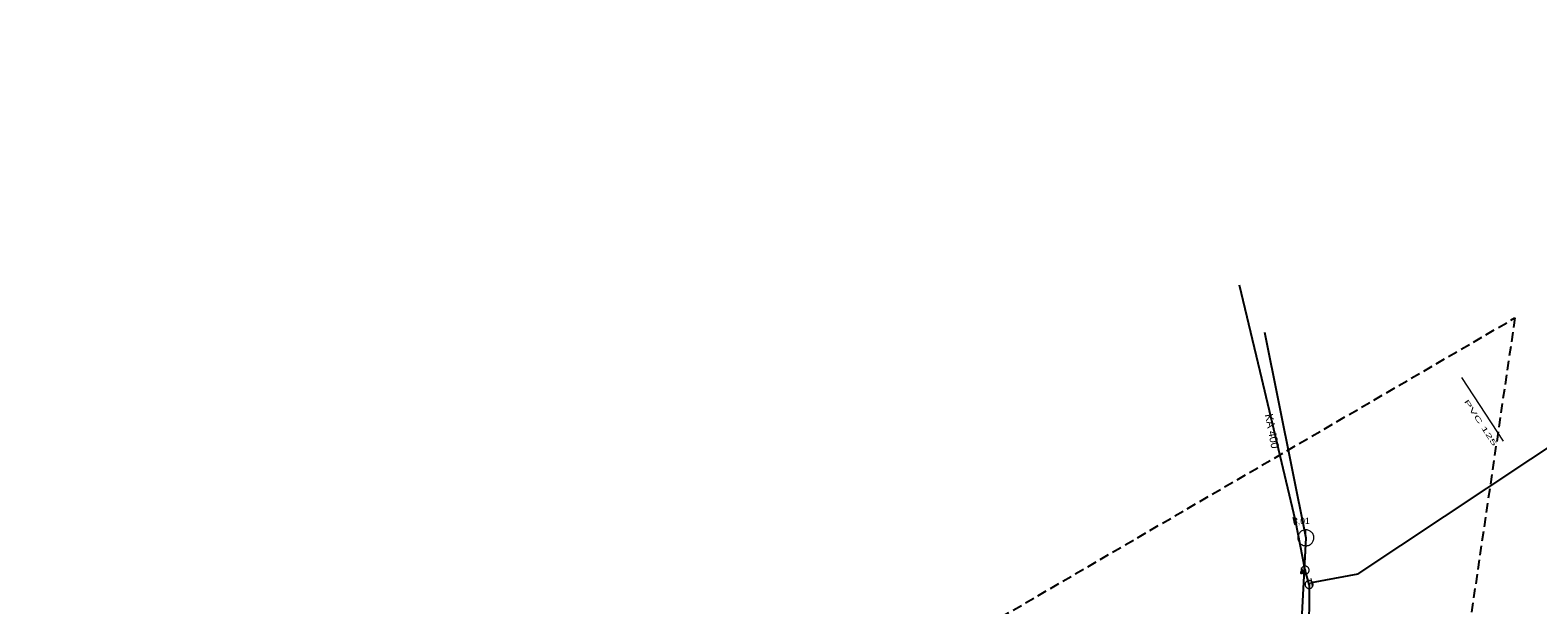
# Model space of a CAD drawing. Extents: x -689189 to -688666, y -973229 to -972850.
# Drawn here: x -688952.7 to -688764.3, y -972922 to -972850.1 of the extents above; entities that cross this region are included whole.
import ezdxf

# ---------------------------------------------------------------- set-up
doc = ezdxf.new("R2010")
doc.units = 0
doc.header["$LTSCALE"] = 0.4
doc.linetypes.add('MEDIUM_DASHED', pattern=[4.5, 3, -1.5])
doc.layers.add('1', color=7, linetype='Continuous')
for name, color, linetype, lineweight in [('11', 7, 'Continuous', 13), ('14', 7, 'Continuous', 13), ('17', 7, 'Continuous', 25), ('22', 7, 'Continuous', 13), ('34', 7, 'Continuous', 13), ('47', 7, 'Continuous', 13), ('63', 7, 'MEDIUM_DASHED', 25), ('9', 7, 'Continuous', 13)]:
    doc.layers.add(name, color=color, linetype=linetype, lineweight=lineweight)

msp = doc.modelspace()

# ---------------------------------------------------------------- linework, layer by layer
at = {"layer": '11'}
msp.add_line((-688773.829, -972893.57), (-688768.609, -972901.5), dxfattribs=at)
at = {"layer": '14', "lineweight": 25}
for p, q in [((-688798.458, -972887.895), (-688793.27, -972913.607)), ((-688793.27, -972913.607), (-688794.848, -972944.059))]:
    msp.add_line(p, q, dxfattribs=at)
at = {"layer": '14'}
for p, q in [((-688794.559, -972911.458), (-688794.779, -972911.519)), ((-688793.649, -972917.78), (-688793.829, -972917.959)), ((-688793.357, -972917.65), (-688793.65, -972917.78)), ((-688792.569, -972919.209), (-688792.866, -972919.454))]:
    msp.add_line(p, q, dxfattribs=at)
at = {"layer": '17'}
for q in [(-688793.357, -972917.649), (-688792.912, -972931.053)]:
    msp.add_line((-688792.866, -972919.454), q, dxfattribs=at)
for points in [[(-688792.569, -972919.209), (-688786.753, -972918.126), (-688749.036, -972893.049), (-688728.665, -972879.484), (-688714.517, -972870.393), (-688697.101, -972861.767), (-688696.793, -972861.66), (-688668.989, -972850.105), (-688665.589, -972858.071)], [(-688793.357, -972917.649), (-688794.559, -972911.458), (-688798.977, -972892.802), (-688801.561, -972882.007)]]:
    msp.add_lwpolyline(points, dxfattribs=at)
at = {"layer": '22'}
msp.add_line((-688793.27, -972915.607), (-688793.269, -972912.607), dxfattribs=at)
msp.add_lwpolyline([(-688792.27, -972913.607), (-688792.275, -972913.498), (-688792.293, -972913.39), (-688792.323, -972913.284), (-688792.363, -972913.183), (-688792.415, -972913.086), (-688792.477, -972912.996), (-688792.549, -972912.913), (-688792.629, -972912.839), (-688792.717, -972912.773), (-688792.811, -972912.718), (-688792.911, -972912.673), (-688793.016, -972912.64), (-688793.123, -972912.618), (-688793.232, -972912.608), (-688793.342, -972912.61), (-688793.45, -972912.624), (-688793.557, -972912.649), (-688793.66, -972912.686), (-688793.758, -972912.735), (-688793.85, -972912.793), (-688793.936, -972912.862), (-688794.013, -972912.939), (-688794.082, -972913.025), (-688794.141, -972913.117), (-688794.189, -972913.215), (-688794.226, -972913.318), (-688794.252, -972913.425), (-688794.266, -972913.533), (-688794.269, -972913.643), (-688794.259, -972913.752), (-688794.238, -972913.859), (-688794.204, -972913.963), (-688794.16, -972914.063), (-688794.105, -972914.158), (-688794.039, -972914.246), (-688793.965, -972914.326), (-688793.882, -972914.398), (-688793.792, -972914.46), (-688793.696, -972914.512), (-688793.594, -972914.553), (-688793.489, -972914.583), (-688793.381, -972914.601), (-688793.271, -972914.607), (-688793.162, -972914.601), (-688793.054, -972914.583), (-688792.949, -972914.554), (-688792.847, -972914.513), (-688792.75, -972914.461), (-688792.66, -972914.399), (-688792.577, -972914.328), (-688792.502, -972914.248), (-688792.437, -972914.16), (-688792.381, -972914.066), (-688792.337, -972913.966), (-688792.303, -972913.862), (-688792.281, -972913.754), (-688792.271, -972913.645)], close=True, dxfattribs=at)
at = {"layer": '34'}
for p, q in [((-688794.914, -972911.037), (-688794.644, -972912)), ((-688793.852, -972917.323), (-688793.446, -972918.237)), ((-688792.637, -972918.713), (-688792.501, -972919.704))]:
    msp.add_line(p, q, dxfattribs=at)
at = {"layer": '47'}
for points in [[(-688793.452, -972917.158), (-688793.502, -972917.171), (-688793.552, -972917.188), (-688793.598, -972917.212), (-688793.643, -972917.239), (-688793.684, -972917.271), (-688793.722, -972917.308), (-688793.755, -972917.348), (-688793.784, -972917.391), (-688793.809, -972917.437), (-688793.829, -972917.486), (-688793.844, -972917.536), (-688793.852, -972917.588), (-688793.856, -972917.64), (-688793.854, -972917.692), (-688793.847, -972917.744), (-688793.834, -972917.794), (-688793.817, -972917.844), (-688793.793, -972917.891), (-688793.766, -972917.935), (-688793.734, -972917.976), (-688793.697, -972918.014), (-688793.657, -972918.048), (-688793.613, -972918.077), (-688793.568, -972918.102), (-688793.519, -972918.121), (-688793.469, -972918.136), (-688793.417, -972918.145), (-688793.365, -972918.148), (-688793.313, -972918.146), (-688793.261, -972918.139), (-688793.211, -972918.126), (-688793.161, -972918.109), (-688793.114, -972918.086), (-688793.07, -972918.058), (-688793.029, -972918.026), (-688792.991, -972917.99), (-688792.957, -972917.95), (-688792.927, -972917.906), (-688792.903, -972917.86), (-688792.884, -972917.811), (-688792.869, -972917.761), (-688792.86, -972917.71), (-688792.857, -972917.657), (-688792.859, -972917.605), (-688792.866, -972917.553), (-688792.879, -972917.503), (-688792.896, -972917.453), (-688792.919, -972917.407), (-688792.947, -972917.362), (-688792.979, -972917.321), (-688793.015, -972917.283), (-688793.055, -972917.25), (-688793.098, -972917.22), (-688793.145, -972917.196), (-688793.194, -972917.176), (-688793.244, -972917.161), (-688793.295, -972917.153), (-688793.348, -972917.149), (-688793.4, -972917.151)], [(-688793.372, -972917.568), (-688793.381, -972917.57), (-688793.388, -972917.573), (-688793.396, -972917.577), (-688793.403, -972917.581), (-688793.41, -972917.587), (-688793.416, -972917.593), (-688793.422, -972917.599), (-688793.427, -972917.606), (-688793.43, -972917.614), (-688793.434, -972917.622), (-688793.436, -972917.63), (-688793.438, -972917.639), (-688793.438, -972917.647), (-688793.439, -972917.655), (-688793.437, -972917.664), (-688793.435, -972917.673), (-688793.432, -972917.68), (-688793.428, -972917.688), (-688793.424, -972917.695), (-688793.418, -972917.702), (-688793.412, -972917.708), (-688793.406, -972917.714), (-688793.399, -972917.719), (-688793.391, -972917.723), (-688793.383, -972917.726), (-688793.375, -972917.728), (-688793.366, -972917.73), (-688793.358, -972917.73), (-688793.35, -972917.731), (-688793.341, -972917.729), (-688793.332, -972917.727), (-688793.325, -972917.724), (-688793.317, -972917.72), (-688793.31, -972917.716), (-688793.303, -972917.71), (-688793.297, -972917.705), (-688793.291, -972917.698), (-688793.286, -972917.691), (-688793.282, -972917.683), (-688793.279, -972917.675), (-688793.277, -972917.667), (-688793.275, -972917.658), (-688793.275, -972917.65), (-688793.274, -972917.642), (-688793.276, -972917.633), (-688793.278, -972917.624), (-688793.281, -972917.617), (-688793.285, -972917.609), (-688793.289, -972917.602), (-688793.295, -972917.595), (-688793.3, -972917.589), (-688793.307, -972917.583), (-688793.314, -972917.578), (-688793.322, -972917.575), (-688793.33, -972917.571), (-688793.338, -972917.569), (-688793.347, -972917.567), (-688793.355, -972917.567), (-688793.363, -972917.566)], [(-688792.67, -972919.914), (-688792.623, -972919.891), (-688792.579, -972919.863), (-688792.538, -972919.831), (-688792.5, -972919.795), (-688792.466, -972919.754), (-688792.437, -972919.711), (-688792.413, -972919.665), (-688792.393, -972919.616), (-688792.379, -972919.566), (-688792.369, -972919.514), (-688792.366, -972919.462), (-688792.368, -972919.41), (-688792.375, -972919.358), (-688792.388, -972919.307), (-688792.405, -972919.258), (-688792.428, -972919.211), (-688792.456, -972919.167), (-688792.489, -972919.125), (-688792.524, -972919.088), (-688792.565, -972919.054), (-688792.608, -972919.025), (-688792.655, -972919), (-688792.703, -972918.981), (-688792.753, -972918.966), (-688792.805, -972918.957), (-688792.857, -972918.954), (-688792.91, -972918.955), (-688792.961, -972918.963), (-688793.012, -972918.976), (-688793.061, -972918.993), (-688793.108, -972919.016), (-688793.152, -972919.044), (-688793.194, -972919.076), (-688793.231, -972919.112), (-688793.265, -972919.153), (-688793.294, -972919.196), (-688793.319, -972919.242), (-688793.339, -972919.29), (-688793.353, -972919.341), (-688793.362, -972919.393), (-688793.365, -972919.445), (-688793.364, -972919.497), (-688793.356, -972919.549), (-688793.343, -972919.6), (-688793.326, -972919.649), (-688793.303, -972919.696), (-688793.275, -972919.74), (-688793.244, -972919.781), (-688793.207, -972919.819), (-688793.166, -972919.853), (-688793.123, -972919.882), (-688793.077, -972919.906), (-688793.029, -972919.926), (-688792.978, -972919.94), (-688792.926, -972919.95), (-688792.874, -972919.953), (-688792.823, -972919.951), (-688792.77, -972919.944), (-688792.719, -972919.931)], [(-688792.833, -972919.529), (-688792.825, -972919.525), (-688792.819, -972919.521), (-688792.812, -972919.516), (-688792.806, -972919.51), (-688792.8, -972919.503), (-688792.796, -972919.496), (-688792.791, -972919.488), (-688792.788, -972919.48), (-688792.786, -972919.472), (-688792.784, -972919.464), (-688792.784, -972919.455), (-688792.784, -972919.446), (-688792.785, -972919.438), (-688792.787, -972919.43), (-688792.79, -972919.421), (-688792.794, -972919.413), (-688792.798, -972919.407), (-688792.803, -972919.4), (-688792.809, -972919.394), (-688792.816, -972919.388), (-688792.823, -972919.384), (-688792.831, -972919.379), (-688792.839, -972919.376), (-688792.847, -972919.373), (-688792.855, -972919.372), (-688792.864, -972919.372), (-688792.873, -972919.372), (-688792.881, -972919.373), (-688792.889, -972919.375), (-688792.898, -972919.378), (-688792.906, -972919.382), (-688792.912, -972919.386), (-688792.919, -972919.391), (-688792.925, -972919.397), (-688792.931, -972919.404), (-688792.936, -972919.411), (-688792.94, -972919.419), (-688792.943, -972919.427), (-688792.946, -972919.435), (-688792.947, -972919.443), (-688792.947, -972919.452), (-688792.947, -972919.461), (-688792.946, -972919.469), (-688792.944, -972919.477), (-688792.941, -972919.486), (-688792.937, -972919.494), (-688792.933, -972919.5), (-688792.928, -972919.507), (-688792.922, -972919.513), (-688792.915, -972919.519), (-688792.908, -972919.524), (-688792.9, -972919.528), (-688792.892, -972919.531), (-688792.884, -972919.533), (-688792.876, -972919.535), (-688792.867, -972919.535), (-688792.858, -972919.535), (-688792.85, -972919.534), (-688792.842, -972919.532)]]:
    msp.add_lwpolyline(points, close=True, dxfattribs=at)
at = {"layer": '63'}
msp.add_lwpolyline([(-689164.065, -973177.51), (-689187.511, -973131.176), (-688767.155, -972886.107), (-688767.155, -972886.107), (-688777.761, -972958.121), (-688777.761, -972958.121), (-688989.335, -973072.002), (-688989.335, -973072.002)], close=True, dxfattribs=at)
at = {"layer": '9'}
for points in [[(-688793.955, -972917.959), (-688793.955, -972917.972), (-688793.953, -972917.985), (-688793.95, -972917.998), (-688793.945, -972918.01), (-688793.939, -972918.022), (-688793.932, -972918.033), (-688793.924, -972918.043), (-688793.914, -972918.053), (-688793.904, -972918.061), (-688793.893, -972918.068), (-688793.881, -972918.074), (-688793.869, -972918.079), (-688793.856, -972918.082), (-688793.843, -972918.084), (-688793.83, -972918.086), (-688793.817, -972918.085), (-688793.804, -972918.083), (-688793.791, -972918.08), (-688793.779, -972918.075), (-688793.767, -972918.069), (-688793.756, -972918.062), (-688793.746, -972918.054), (-688793.736, -972918.044), (-688793.728, -972918.034), (-688793.721, -972918.023), (-688793.715, -972918.011), (-688793.71, -972917.999), (-688793.707, -972917.986), (-688793.705, -972917.973), (-688793.703, -972917.96), (-688793.704, -972917.947), (-688793.706, -972917.934), (-688793.709, -972917.921), (-688793.714, -972917.909), (-688793.72, -972917.897), (-688793.727, -972917.886), (-688793.735, -972917.876), (-688793.745, -972917.866), (-688793.755, -972917.858), (-688793.766, -972917.851), (-688793.778, -972917.845), (-688793.79, -972917.84), (-688793.803, -972917.837), (-688793.816, -972917.835), (-688793.829, -972917.834), (-688793.842, -972917.834), (-688793.855, -972917.836), (-688793.868, -972917.839), (-688793.88, -972917.844), (-688793.892, -972917.85), (-688793.903, -972917.857), (-688793.913, -972917.865), (-688793.923, -972917.875), (-688793.931, -972917.885), (-688793.938, -972917.896), (-688793.944, -972917.908), (-688793.949, -972917.92), (-688793.952, -972917.933), (-688793.954, -972917.946)], [(-688793.935, -972917.959), (-688793.936, -972917.97), (-688793.934, -972917.981), (-688793.931, -972917.992), (-688793.927, -972918.002), (-688793.922, -972918.012), (-688793.916, -972918.021), (-688793.909, -972918.03), (-688793.901, -972918.038), (-688793.892, -972918.045), (-688793.883, -972918.051), (-688793.873, -972918.056), (-688793.863, -972918.06), (-688793.852, -972918.063), (-688793.841, -972918.066), (-688793.83, -972918.066), (-688793.819, -972918.066), (-688793.808, -972918.064), (-688793.797, -972918.061), (-688793.787, -972918.057), (-688793.777, -972918.052), (-688793.768, -972918.046), (-688793.759, -972918.039), (-688793.751, -972918.031), (-688793.744, -972918.022), (-688793.738, -972918.013), (-688793.733, -972918.003), (-688793.729, -972917.993), (-688793.726, -972917.982), (-688793.724, -972917.971), (-688793.723, -972917.96), (-688793.723, -972917.949), (-688793.725, -972917.938), (-688793.728, -972917.927), (-688793.732, -972917.917), (-688793.737, -972917.907), (-688793.743, -972917.898), (-688793.75, -972917.889), (-688793.758, -972917.881), (-688793.767, -972917.874), (-688793.776, -972917.868), (-688793.786, -972917.863), (-688793.796, -972917.859), (-688793.807, -972917.856), (-688793.818, -972917.854), (-688793.829, -972917.854), (-688793.84, -972917.853), (-688793.851, -972917.855), (-688793.862, -972917.858), (-688793.872, -972917.862), (-688793.882, -972917.867), (-688793.891, -972917.873), (-688793.9, -972917.88), (-688793.908, -972917.888), (-688793.915, -972917.897), (-688793.921, -972917.906), (-688793.926, -972917.916), (-688793.93, -972917.926), (-688793.933, -972917.937), (-688793.935, -972917.948)], [(-688793.916, -972917.959), (-688793.916, -972917.968), (-688793.915, -972917.977), (-688793.912, -972917.986), (-688793.909, -972917.994), (-688793.905, -972918.002), (-688793.9, -972918.01), (-688793.894, -972918.017), (-688793.888, -972918.023), (-688793.881, -972918.029), (-688793.873, -972918.034), (-688793.865, -972918.038), (-688793.857, -972918.041), (-688793.848, -972918.044), (-688793.839, -972918.045), (-688793.83, -972918.047), (-688793.821, -972918.046), (-688793.812, -972918.045), (-688793.803, -972918.042), (-688793.795, -972918.039), (-688793.787, -972918.035), (-688793.779, -972918.03), (-688793.772, -972918.024), (-688793.766, -972918.018), (-688793.76, -972918.011), (-688793.755, -972918.003), (-688793.751, -972917.995), (-688793.748, -972917.987), (-688793.745, -972917.978), (-688793.744, -972917.969), (-688793.742, -972917.96), (-688793.743, -972917.951), (-688793.744, -972917.942), (-688793.747, -972917.933), (-688793.75, -972917.925), (-688793.754, -972917.917), (-688793.759, -972917.909), (-688793.765, -972917.902), (-688793.771, -972917.896), (-688793.778, -972917.89), (-688793.786, -972917.885), (-688793.794, -972917.881), (-688793.802, -972917.878), (-688793.811, -972917.875), (-688793.82, -972917.874), (-688793.829, -972917.873), (-688793.838, -972917.873), (-688793.847, -972917.874), (-688793.856, -972917.877), (-688793.864, -972917.88), (-688793.872, -972917.884), (-688793.88, -972917.889), (-688793.887, -972917.895), (-688793.893, -972917.901), (-688793.899, -972917.908), (-688793.904, -972917.916), (-688793.908, -972917.924), (-688793.911, -972917.932), (-688793.914, -972917.941), (-688793.915, -972917.95)], [(-688793.896, -972917.959), (-688793.896, -972917.966), (-688793.895, -972917.973), (-688793.894, -972917.98), (-688793.891, -972917.986), (-688793.888, -972917.992), (-688793.884, -972917.998), (-688793.88, -972918.004), (-688793.875, -972918.009), (-688793.869, -972918.013), (-688793.863, -972918.017), (-688793.857, -972918.02), (-688793.851, -972918.023), (-688793.844, -972918.024), (-688793.837, -972918.027), (-688793.83, -972918.027), (-688793.823, -972918.027), (-688793.816, -972918.025), (-688793.809, -972918.024), (-688793.803, -972918.021), (-688793.796, -972918.018), (-688793.791, -972918.014), (-688793.785, -972918.01), (-688793.78, -972918.005), (-688793.776, -972917.999), (-688793.772, -972917.993), (-688793.769, -972917.987), (-688793.766, -972917.981), (-688793.764, -972917.974), (-688793.763, -972917.967), (-688793.762, -972917.96), (-688793.762, -972917.953), (-688793.763, -972917.946), (-688793.765, -972917.939), (-688793.768, -972917.933), (-688793.771, -972917.926), (-688793.775, -972917.921), (-688793.779, -972917.915), (-688793.784, -972917.91), (-688793.79, -972917.906), (-688793.795, -972917.902), (-688793.802, -972917.899), (-688793.808, -972917.896), (-688793.815, -972917.894), (-688793.822, -972917.893), (-688793.829, -972917.893), (-688793.836, -972917.893), (-688793.843, -972917.893), (-688793.85, -972917.895), (-688793.856, -972917.898), (-688793.862, -972917.901), (-688793.868, -972917.905), (-688793.874, -972917.909), (-688793.879, -972917.914), (-688793.883, -972917.92), (-688793.887, -972917.925), (-688793.89, -972917.932), (-688793.893, -972917.938), (-688793.894, -972917.945), (-688793.896, -972917.952)], [(-688793.876, -972917.959), (-688793.876, -972917.964), (-688793.876, -972917.969), (-688793.875, -972917.974), (-688793.873, -972917.978), (-688793.871, -972917.983), (-688793.868, -972917.987), (-688793.865, -972917.99), (-688793.861, -972917.994), (-688793.858, -972917.997), (-688793.854, -972918), (-688793.849, -972918.002), (-688793.845, -972918.004), (-688793.84, -972918.005), (-688793.835, -972918.007), (-688793.83, -972918.007), (-688793.825, -972918.007), (-688793.82, -972918.006), (-688793.815, -972918.005), (-688793.811, -972918.003), (-688793.806, -972918.001), (-688793.802, -972917.998), (-688793.798, -972917.995), (-688793.795, -972917.991), (-688793.792, -972917.988), (-688793.789, -972917.984), (-688793.787, -972917.979), (-688793.785, -972917.975), (-688793.784, -972917.97), (-688793.783, -972917.965), (-688793.782, -972917.96), (-688793.782, -972917.955), (-688793.783, -972917.95), (-688793.784, -972917.945), (-688793.786, -972917.941), (-688793.788, -972917.936), (-688793.791, -972917.932), (-688793.794, -972917.928), (-688793.797, -972917.925), (-688793.801, -972917.922), (-688793.805, -972917.919), (-688793.81, -972917.917), (-688793.814, -972917.915), (-688793.819, -972917.914), (-688793.824, -972917.913), (-688793.829, -972917.913), (-688793.834, -972917.913), (-688793.839, -972917.914), (-688793.844, -972917.914), (-688793.848, -972917.916), (-688793.853, -972917.918), (-688793.857, -972917.921), (-688793.86, -972917.924), (-688793.864, -972917.927), (-688793.867, -972917.931), (-688793.87, -972917.935), (-688793.872, -972917.94), (-688793.874, -972917.944), (-688793.875, -972917.949), (-688793.876, -972917.954)], [(-688793.856, -972917.959), (-688793.856, -972917.962), (-688793.857, -972917.965), (-688793.856, -972917.967), (-688793.855, -972917.97), (-688793.854, -972917.973), (-688793.852, -972917.975), (-688793.85, -972917.977), (-688793.848, -972917.979), (-688793.846, -972917.981), (-688793.844, -972917.983), (-688793.841, -972917.985), (-688793.838, -972917.986), (-688793.836, -972917.986), (-688793.833, -972917.987), (-688793.83, -972917.987), (-688793.827, -972917.987), (-688793.824, -972917.987), (-688793.821, -972917.986), (-688793.819, -972917.985), (-688793.816, -972917.984), (-688793.814, -972917.982), (-688793.811, -972917.98), (-688793.809, -972917.978), (-688793.808, -972917.976), (-688793.806, -972917.974), (-688793.805, -972917.971), (-688793.803, -972917.968), (-688793.803, -972917.966), (-688793.802, -972917.963), (-688793.801, -972917.96), (-688793.802, -972917.957), (-688793.802, -972917.954), (-688793.803, -972917.951), (-688793.804, -972917.949), (-688793.805, -972917.946), (-688793.807, -972917.944), (-688793.808, -972917.941), (-688793.81, -972917.939), (-688793.813, -972917.938), (-688793.815, -972917.936), (-688793.818, -972917.935), (-688793.82, -972917.934), (-688793.823, -972917.933), (-688793.826, -972917.933), (-688793.829, -972917.932), (-688793.832, -972917.933), (-688793.835, -972917.932), (-688793.837, -972917.934), (-688793.84, -972917.934), (-688793.843, -972917.935), (-688793.845, -972917.937), (-688793.847, -972917.938), (-688793.849, -972917.94), (-688793.851, -972917.943), (-688793.853, -972917.945), (-688793.854, -972917.948), (-688793.855, -972917.95), (-688793.856, -972917.953), (-688793.856, -972917.956)], [(-688793.837, -972917.959), (-688793.837, -972917.961), (-688793.837, -972917.961), (-688793.836, -972917.961), (-688793.836, -972917.963), (-688793.837, -972917.964), (-688793.835, -972917.964), (-688793.835, -972917.964), (-688793.835, -972917.966), (-688793.835, -972917.966), (-688793.834, -972917.967), (-688793.832, -972917.967), (-688793.832, -972917.967), (-688793.832, -972917.968), (-688793.83, -972917.968), (-688793.83, -972917.968), (-688793.829, -972917.968), (-688793.828, -972917.968), (-688793.828, -972917.967), (-688793.827, -972917.967), (-688793.825, -972917.967), (-688793.825, -972917.966), (-688793.825, -972917.966), (-688793.824, -972917.965), (-688793.824, -972917.965), (-688793.822, -972917.964), (-688793.822, -972917.963), (-688793.821, -972917.962), (-688793.821, -972917.962), (-688793.821, -972917.961), (-688793.821, -972917.96), (-688793.821, -972917.959), (-688793.821, -972917.958), (-688793.821, -972917.958), (-688793.822, -972917.957), (-688793.822, -972917.956), (-688793.823, -972917.955), (-688793.823, -972917.955), (-688793.824, -972917.954), (-688793.824, -972917.954), (-688793.825, -972917.953), (-688793.826, -972917.953), (-688793.827, -972917.952), (-688793.827, -972917.952), (-688793.828, -972917.952), (-688793.829, -972917.952), (-688793.83, -972917.952), (-688793.831, -972917.952), (-688793.831, -972917.952), (-688793.832, -972917.953), (-688793.833, -972917.952), (-688793.834, -972917.954), (-688793.834, -972917.954), (-688793.835, -972917.954), (-688793.835, -972917.954), (-688793.836, -972917.956), (-688793.836, -972917.957), (-688793.836, -972917.958), (-688793.837, -972917.958), (-688793.837, -972917.959)]]:
    msp.add_lwpolyline(points, close=True, dxfattribs=at)

# ---------------------------------------------------------------- texts
at = {"layer": '1', "width": 2.1}
msp.add_text('PVC 125 ', height=0.6, rotation=303, dxfattribs=at).set_placement((-688773.536, -972896.544))
at = {"layer": '1'}
msp.add_text('KA 400', height=1, rotation=281, dxfattribs=at).set_placement((-688798.402, -972898.203))
msp.add_text('3,01', height=0.8, dxfattribs=at).set_placement((-688794.869, -972911.896))

doc.saveas('drawing.dxf')
